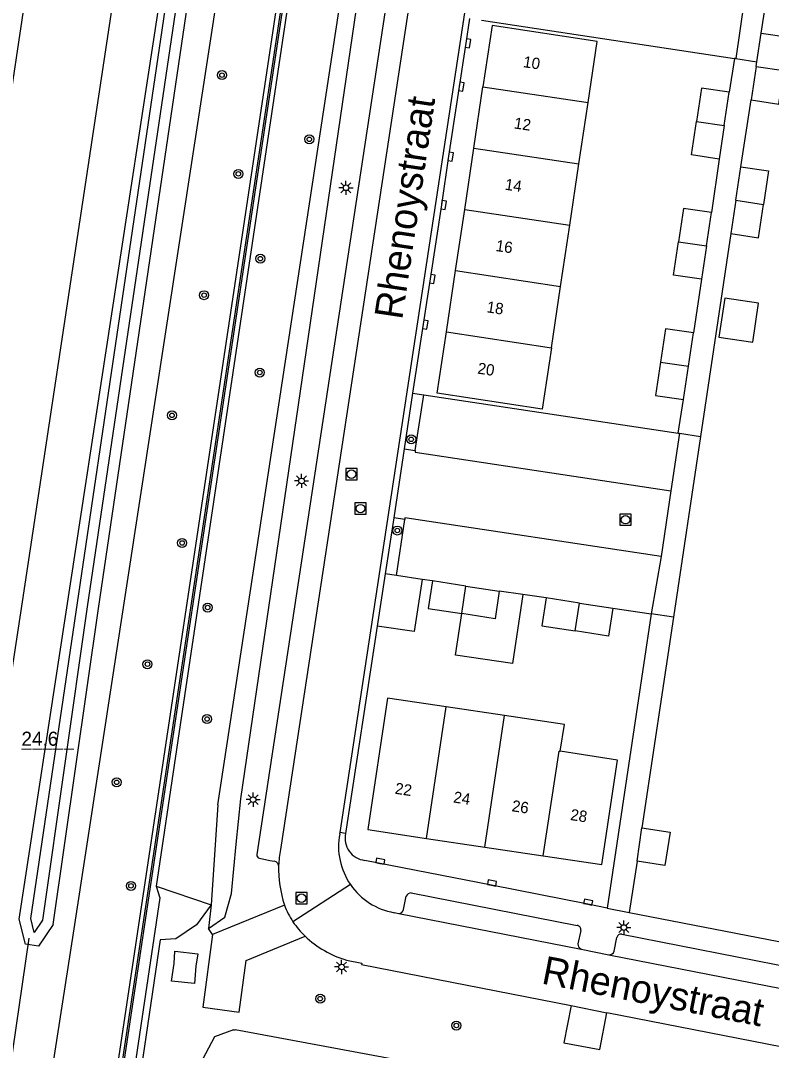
# Model space of a CAD drawing. Extents: x 124000 to 128010, y 398999 to 403000.
# Drawn here: x 126320.1 to 126386.8, y 399650.9 to 399742.3 of the extents above; entities that cross this region are included whole.
import ezdxf

# ---------------------------------------------------------------- set-up
doc = ezdxf.new("R2010")
doc.units = 0
for name, color, linetype in [('gg-afsc-erfafscheiding', 7, 'Continuous'), ('gg-afsc-geluidsscherm', 7, 'Continuous'), ('gg-afsc-hekwerk', 7, 'Continuous'), ('gg-anno-huisnummerreeks BGT', 7, 'Continuous'), ('gg-anno-openbare ruimte label', 7, 'Continuous'), ('gg-bbg-bijgebouw', 7, 'Continuous'), ('gg-bbg-gedigitaliseerde bijgebouw', 7, 'Continuous'), ('gg-bbg-hoofdgebouw', 7, 'Continuous'), ('gg-bbg-lage trafo', 7, 'Continuous'), ('gg-bbg-luifel en loopbrug', 7, 'Continuous'), ('gg-bbg-tussenscheiding', 7, 'Continuous'), ('gg-knt-BGT kruinlijn', 7, 'Continuous'), ('gg-knt-bovenkant onderkant talud', 7, 'Continuous'), ('gg-knt-verharding', 7, 'Continuous'), ('gg-knt-verharding nz', 7, 'Continuous'), ('gg-kntw-bovenkant insteek waterloop', 7, 'Continuous'), ('gg-kntw-waterlijn', 7, 'Continuous'), ('gg-kwrk-duiker nz buis', 7, 'Continuous'), ('gt-anno-nummer hm paal', 7, 'Continuous'), ('gt-grn-groengrens', 7, 'Continuous'), ('gt-grn-weggrens', 7, 'Continuous'), ('gt-symb-boom', 7, 'Continuous'), ('gt-symb-hm paal', 7, 'Continuous'), ('gt-symb-kolk', 7, 'Continuous'), ('gt-symb-lichtmast', 7, 'Continuous'), ('gt-symb-rioolschacht', 7, 'Continuous'), ('gx-grn-maaiveld', 7, 'Continuous')]:
    doc.layers.add(name, color=color, linetype=linetype)

# ---------------------------------------------------------------- blocks, each defined once
blk = doc.blocks.new('gt0-BOOM')
at = {"layer": 'gt-symb-boom'}
for radius in [0.4, 0.2]:
    blk.add_circle((0, 0), radius, dxfattribs=at)
blk = doc.blocks.new('gt0-RS')
at = {"layer": 'gt-symb-rioolschacht'}
blk.add_lwpolyline([(-0.5, -0.5), (0.5, -0.5), (0.5, 0.5), (-0.5, 0.5)], close=True, dxfattribs=at)
blk.add_circle((0, 0), 0.375, dxfattribs=at)
blk = doc.blocks.new('gt0-KOLK')
at = {"layer": 'gt-symb-kolk'}
blk.add_lwpolyline([(0, 0), (0.375, 0), (0.375, 0.4), (-0.375, 0.4), (-0.375, 0), (0, 0)], dxfattribs=at)
blk = doc.blocks.new('gt0-LMAST')
at = {"layer": 'gt-symb-lichtmast'}
for p, q in [((-0.182, 0.173), (-0.447, 0.438)), ((-0.005, 0.246), (-0.005, 0.621)), ((0.172, 0.173), (0.437, 0.438)), ((-0.255, -0.004), (-0.63, -0.004)), ((-0.182, -0.181), (-0.447, -0.446)), ((-0.005, -0.254), (-0.005, -0.629)), ((0.437, -0.446), (0.172, -0.181)), ((0.245, -0.004), (0.62, -0.004))]:
    blk.add_line(p, q, dxfattribs=at)
blk.add_circle((-0.005, -0.004), 0.25, dxfattribs=at)

msp = doc.modelspace()

# ---------------------------------------------------------------- linework, layer by layer
at = {"layer": 'gg-afsc-erfafscheiding'}
msp.add_line((126354.925, 399709.208), (126355.932, 399709.051), dxfattribs=at)
at = {"layer": 'gg-afsc-geluidsscherm'}
for points in [[(126433.522, 399396.193), (126294.266, 399417.89), (126294.312, 399418.568), (126384.69, 400018.495), (126392.393, 400081.874), (126401.389, 400173.179), (126405.812, 400237.067), (126415.183, 400254.387), (126416.933, 400270.191), (126421.505, 400378.061), (126422.448, 400394.046), (126423.962, 400411.149), (126518.093, 400411.476), (126531.613, 400399.449), (126531.513, 400399.337)], [(126433.522, 399396.193), (126433.545, 399396.341), (126294.438, 399418.015), (126294.46, 399418.546), (126384.838, 400018.472), (126392.542, 400081.856), (126401.538, 400173.164), (126405.962, 400237.057), (126415.315, 400254.315), (126417.082, 400270.175), (126421.655, 400378.055), (126422.598, 400394.037), (126424.098, 400410.986), (126518.093, 400411.326), (126531.513, 400399.337)]]:
    msp.add_lwpolyline(points, dxfattribs=at)
at = {"layer": 'gg-afsc-hekwerk'}
for p, q in [((126385.859, 399741.164), (126386.316, 399744.206)), ((126384.062, 399729.288), (126384.963, 399735.23)), ((126382.14, 399729.98), (126381.438, 399725.232)), ((126383.164, 399723.354), (126380.473, 399705.355)), ((126380.55, 399719.305), (126379.841, 399714.554)), ((126380.473, 399705.355), (126378.074, 399689.313)), ((126366.765, 399691.018), (126364.705, 399691.322)), ((126378.074, 399689.313), (126375.279, 399670.617)), ((126374.847, 399667.652), (126374.143, 399663.098)), ((126374.143, 399663.098), (126388.339, 399660.336))]:
    msp.add_line(p, q, dxfattribs=at)
at = {"layer": 'gg-bbg-bijgebouw'}
for p, q in [((126385.475, 399738.618), (126385.859, 399741.164)), ((126385.859, 399741.164), (126388.311, 399740.794)), ((126385.411, 399738.197), (126384.963, 399735.23)), ((126385.411, 399738.197), (126385.475, 399738.618)), ((126382.585, 399732.943), (126383.03, 399735.906)), ((126382.585, 399732.943), (126382.14, 399729.98)), ((126383.613, 399726.321), (126384.062, 399729.288)), ((126383.613, 399726.321), (126383.164, 399723.354)), ((126380.994, 399722.269), (126381.438, 399725.232)), ((126380.994, 399722.269), (126380.55, 399719.305)), ((126379.396, 399711.591), (126379.841, 399714.554)), ((126378.95, 399708.628), (126379.396, 399711.591)), ((126359.652, 399692.079), (126356.689, 399692.526)), ((126359.652, 399692.079), (126362.615, 399691.631)), ((126369.729, 399690.56), (126366.765, 399691.018)), ((126369.729, 399690.56), (126372.692, 399690.103)), ((126374.847, 399667.652), (126375.279, 399670.617)), ((126377.299, 399667.261), (126374.847, 399667.652))]:
    msp.add_line(p, q, dxfattribs=at)
for points in [[(126384.963, 399735.23), (126387.415, 399734.86), (126387.863, 399737.827)], [(126383.03, 399735.906), (126380.568, 399736.276), (126380.123, 399733.313)], [(126382.14, 399729.98), (126379.678, 399730.35), (126380.123, 399733.313)], [(126384.062, 399729.288), (126386.515, 399728.917), (126386.066, 399725.949)], [(126383.164, 399723.354), (126385.617, 399722.981), (126386.066, 399725.949)], [(126381.438, 399725.232), (126378.975, 399725.601), (126378.531, 399722.638)], [(126380.55, 399719.305), (126378.087, 399719.674), (126378.531, 399722.638)], [(126379.841, 399714.554), (126377.376, 399714.921), (126376.935, 399711.958)], [(126376.935, 399711.958), (126376.493, 399708.994), (126378.95, 399708.628)], [(126356.689, 399692.526), (126356.319, 399690.075), (126359.285, 399689.627)], [(126362.615, 399691.631), (126362.25, 399689.179), (126359.285, 399689.627)], [(126366.765, 399691.018), (126366.384, 399688.55), (126369.347, 399688.092)], [(126372.692, 399690.103), (126372.309, 399687.635), (126369.347, 399688.092)], [(126375.279, 399670.617), (126377.771, 399670.22), (126377.299, 399667.261)]]:
    msp.add_lwpolyline(points, dxfattribs=at)
at = {"layer": 'gg-bbg-gedigitaliseerde bijgebouw'}
msp.add_lwpolyline([(126382.114, 399714.166), (126385.119, 399713.721), (126385.631, 399717.179), (126382.626, 399717.624), (126382.114, 399714.166)], dxfattribs=at)
at = {"layer": 'gg-bbg-hoofdgebouw'}
for p, q in [((126360.357, 399730.95), (126361.166, 399736.391)), ((126369.683, 399729.544), (126370.498, 399734.983)), ((126359.547, 399725.51), (126360.357, 399730.95)), ((126368.867, 399724.105), (126369.683, 399729.544)), ((126358.737, 399720.07), (126359.547, 399725.51)), ((126368.051, 399718.666), (126368.867, 399724.105)), ((126357.928, 399714.629), (126358.737, 399720.07)), ((126367.236, 399713.227), (126368.051, 399718.666)), ((126363.087, 399680.578), (126357.9, 399681.356)), ((126356.15, 399669.683), (126361.337, 399668.906)), ((126361.337, 399668.906), (126366.524, 399668.128))]:
    msp.add_line(p, q, dxfattribs=at)
for points in [[(126370.498, 399734.983), (126371.314, 399740.422), (126361.976, 399741.831), (126361.166, 399736.391)], [(126367.236, 399713.227), (126366.42, 399707.788), (126357.118, 399709.189), (126357.928, 399714.629)], [(126357.9, 399681.356), (126352.71, 399682.135), (126350.963, 399670.461), (126356.15, 399669.683)], [(126368.026, 399677.414), (126368.39, 399679.782), (126363.087, 399680.578)], [(126366.524, 399668.128), (126371.711, 399667.35), (126373.104, 399676.624), (126368.026, 399677.414)]]:
    msp.add_lwpolyline(points, dxfattribs=at)
at = {"layer": 'gg-bbg-lage trafo'}
msp.add_lwpolyline([(126333.543, 399657.013), (126333.77, 399658.569), (126333.839, 399659.673), (126335.872, 399659.44), (126335.679, 399658.351), (126335.557, 399656.786), (126333.543, 399657.013)], dxfattribs=at)
at = {"layer": 'gg-bbg-luifel en loopbrug'}
for p, q in [((126352.494, 399693.17), (126351.784, 399688.516)), ((126353.498, 399693.015), (126352.494, 399693.17)), ((126355.759, 399692.669), (126353.498, 399693.015)), ((126364.705, 399691.322), (126362.615, 399691.631))]:
    msp.add_line(p, q, dxfattribs=at)
for points in [[(126355.759, 399692.669), (126355.072, 399688.03), (126351.784, 399688.516)], [(126364.705, 399691.322), (126363.798, 399685.196), (126358.74, 399685.945), (126359.285, 399689.627)]]:
    msp.add_lwpolyline(points, dxfattribs=at)
at = {"layer": 'gg-bbg-tussenscheiding'}
for p, q in [((126385.411, 399738.197), (126387.863, 399737.827)), ((126361.166, 399736.391), (126370.498, 399734.983)), ((126380.123, 399733.313), (126382.585, 399732.943)), ((126360.357, 399730.95), (126369.683, 399729.544)), ((126383.613, 399726.321), (126386.066, 399725.949)), ((126359.547, 399725.51), (126368.867, 399724.105)), ((126378.531, 399722.638), (126380.994, 399722.269)), ((126358.737, 399720.07), (126368.051, 399718.666)), ((126357.928, 399714.629), (126367.236, 399713.227)), ((126376.935, 399711.958), (126379.396, 399711.591)), ((126359.285, 399689.627), (126359.652, 399692.079)), ((126369.347, 399688.092), (126369.729, 399690.56)), ((126356.15, 399669.683), (126357.9, 399681.356)), ((126361.337, 399668.906), (126363.087, 399680.578))]:
    msp.add_line(p, q, dxfattribs=at)
msp.add_lwpolyline([(126366.524, 399668.128), (126367.919, 399677.43), (126368.026, 399677.414)], dxfattribs=at)
at = {"layer": 'gg-knt-BGT kruinlijn'}
for points in [[(126300.242, 399460.061), (126317.155, 399573.618), (126327.853, 399643.472), (126345.991, 399764.256), (126377.209, 399971.201), (126384.168, 400018.601), (126391.597, 400079.17), (126401.015, 400171.969), (126405.272, 400237.075), (126405.836, 400239.447)], [(126405.997, 400230.826), (126401.252, 400165.313), (126397.513, 400125.164), (126394.977, 400098.805), (126384.91, 400016.956), (126372.958, 399936.144), (126361.724, 399862.808), (126350.889, 399790.817), (126334.29, 399679.75), (126332.168, 399665.424)], [(126332.168, 399665.424), (126332.505, 399664.403), (126326.997, 399627.412), (126326.354, 399625.57), (126325.748, 399624.249), (126321.63, 399595.513), (126311.054, 399526.142)]]:
    msp.add_lwpolyline(points, dxfattribs=at)
at = {"layer": 'gg-knt-bovenkant onderkant talud'}
for points in [[(126293.229, 399462.196), (126310.804, 399577.419), (126321.785, 399641.664), (126324.83, 399661.281), (126341.384, 399769.192), (126355.148, 399863.606), (126371.991, 399972.892), (126378.989, 400019.753), (126385.648, 400077.466), (126395.494, 400171.208), (126398.482, 400218.678), (126399.195, 400237.176), (126399.855, 400244.875), (126401.075, 400247.387), (126403.954, 400253.411), (126406.57, 400258.304), (126407.848, 400260.608), (126408.109, 400271.651), (126414.004, 400375.395), (126416.291, 400410.556)], [(126337.055, 399663.773), (126335.755, 399661.999), (126333.916, 399660.765), (126332.52, 399660.668), (126328.5, 399633.374), (126331.078, 399632.608), (126332.337, 399630.998), (126332.355, 399628.505), (126332.067, 399624.359)]]:
    msp.add_lwpolyline(points, dxfattribs=at)
at = {"layer": 'gg-knt-verharding'}
for p, q in [((126358.524, 399782.884), (126341.103, 399668.24)), ((126365.333, 399781.244), (126348.47, 399670.193)), ((126361.027, 399742.312), (126383.477, 399738.908)), ((126383.477, 399738.908), (126383.03, 399735.906)), ((126354.925, 399709.208), (126354.184, 399704.255)), ((126355.164, 399704.1), (126355.932, 399709.051)), ((126355.932, 399709.051), (126378.483, 399705.646)), ((126378.483, 399705.646), (126378.95, 399708.628)), ((126354.184, 399704.255), (126353.264, 399698.132)), ((126354.184, 399704.255), (126355.164, 399704.1)), ((126353.264, 399698.132), (126352.494, 399693.17)), ((126354.227, 399697.992), (126353.264, 399698.132)), ((126353.498, 399693.015), (126354.227, 399697.992)), ((126356.689, 399692.526), (126355.759, 399692.669)), ((126376.102, 399689.608), (126372.187, 399663.477)), ((126372.692, 399690.103), (126376.102, 399689.608)), ((126351.784, 399688.516), (126348.979, 399670.116)), ((126348.47, 399670.193), (126348.452, 399670.077)), ((126354.808, 399664.855), (126369.532, 399661.949)), ((126354.107, 399663.362), (126354.346, 399664.56)), ((126343.55, 399663.755), (126337.181, 399661.137)), ((126353.283, 399663.086), (126353.692, 399663.023)), ((126369.841, 399661.511), (126369.601, 399660.328)), ((126373.493, 399661.176), (126392.88, 399657.377)), ((126372.803, 399659.672), (126373.045, 399660.867)), ((126369.889, 399659.857), (126372.35, 399659.355)), ((126368.983, 399654.835), (126372.169, 399654.21))]:
    msp.add_line(p, q, dxfattribs=at)
for points in [[(126367.407, 400062.712), (126364.322, 400037.875), (126361.171, 400013.803), (126357.829, 399990.064), (126353.282, 399959.93), (126347.871, 399924.53), (126341.915, 399884.96), (126328.842, 399798.709), (126320.556, 399744.349), (126316.646, 399718.33), (126308.838, 399667.237), (126306.683, 399653.03)], [(126375.086, 400061.828), (126371.995, 400036.99), (126368.895, 400013.208), (126365.235, 399987.425), (126360.949, 399959.247), (126355.621, 399923.874), (126349.501, 399883.525), (126345.75, 399858.978), (126340.485, 399824.032), (126332.179, 399769.496), (126320.274, 399690.665), (126316.376, 399665.179), (126314.314, 399651.556)], [(126359.971, 399742.46), (126359.648, 399740.27), (126358.108, 399730.22), (126357.475, 399725.922), (126356.48, 399719.357), (126354.925, 399709.208)], [(126341.332, 399667.91), (126342.253, 399667.727), (126342.674, 399667.655)], [(126372.187, 399663.477), (126370.46, 399663.829), (126361.934, 399665.524), (126350.683, 399667.726)], [(126337.181, 399661.137), (126336.308, 399654.686), (126339.521, 399654.242), (126340.158, 399658.849), (126345.381, 399661.006)], [(126349.07, 399658.868), (126350.412, 399658.601), (126350.392, 399658.482), (126368.983, 399654.835)], [(126368.983, 399654.835), (126368.337, 399651.539), (126371.526, 399650.931), (126372.169, 399654.21)]]:
    msp.add_lwpolyline(points, dxfattribs=at)
for centre, radius, start, end in [((126354.336, 399668.979), 5.985, 169.42979, 214.65017), ((126350.914, 399669.693), 1.98, 167.66224, 263.31327), ((126341.409, 399668.208), 0.308, 174.02699, 255.48962), ((126342.592, 399667.217), 0.446, 7.50771, 79.39598), ((126353.729, 399667.045), 10.698, 178.76805, 197.91124), ((126354.336, 399668.977), 5.985, 214.63463, 259.8635), ((126354.898, 399664.205), 0.656, 97.85434, 147.26441), ((126350.513, 399666.401), 7.449, 200.80731, 213.6179), ((126353.704, 399663.432), 0.409, 268.2899, 350.19863), ((126350.499, 399666.405), 7.44, 213.7054, 226.5325), ((126369.494, 399661.594), 0.357, 346.57793, 83.82644), ((126373.412, 399660.815), 0.37, 77.30992, 171.88064), ((126351.573, 399667.439), 8.929, 226.09177, 253.71843), ((126370.015, 399660.258), 0.42, 170.33419, 252.55446), ((126372.39, 399659.78), 0.427, 264.61356, 345.3535)]:
    msp.add_arc(centre, radius, start, end, dxfattribs=at)
at = {"layer": 'gg-knt-verharding nz'}
for p, q in [((126360.622, 399783.283), (126343.194, 399668.685)), ((126384.357, 399744.016), (126383.599, 399738.898)), ((126383.599, 399738.898), (126383.477, 399738.908)), ((126378.597, 399705.635), (126377.843, 399700.526)), ((126378.483, 399705.646), (126378.597, 399705.635)), ((126377.843, 399700.526), (126376.971, 399694.698)), ((126376.971, 399694.698), (126376.102, 399689.608)), ((126348.979, 399670.116), (126348.47, 399670.193)), ((126353.692, 399663.023), (126369.889, 399659.857)), ((126372.35, 399659.355), (126393.193, 399655.272))]:
    msp.add_line(p, q, dxfattribs=at)
for points in [[(126355.164, 399704.1), (126355.148, 399703.962), (126377.843, 399700.526)], [(126376.971, 399694.698), (126354.241, 399698.118), (126354.227, 399697.992)]]:
    msp.add_lwpolyline(points, dxfattribs=at)
msp.add_arc((126355.025, 399666.628), 12.009, 170.13884, 176.91325, dxfattribs=at)
at = {"layer": 'gg-kntw-bovenkant insteek waterloop'}
for p, q in [((126337.653, 399672.667), (126337.055, 399663.773)), ((126337.055, 399663.773), (126336.819, 399661.669))]:
    msp.add_line(p, q, dxfattribs=at)
for points in [[(126323.031, 399662.04), (126321.74, 399660.117), (126320.587, 399660.289), (126320.014, 399662.511), (126332.334, 399743.098), (126336.188, 399768.41), (126344.467, 399823.06), (126353.306, 399883.083), (126359.695, 399923.364), (126365.113, 399959.07), (126369.177, 399986.373), (126372.735, 400012.848), (126375.768, 400035.991), (126379.045, 400062.476), (126382.001, 400085.384), (126384.826, 400114.553), (126387.163, 400137.912), (126389.716, 400166.128), (126391.77, 400193.942), (126393.76, 400220.612), (126395.587, 400247.464), (126396.695, 400267.432)], [(126323.031, 399662.04), (126327.041, 399690.098), (126334.838, 399742.841), (126338.537, 399768.285), (126342.893, 399797.119), (126346.686, 399823.411), (126352.294, 399859.144), (126356.486, 399884.03), (126360.061, 399908.445), (126363.653, 399932.302), (126367.208, 399956.505), (126370.042, 399973.218), (126373.244, 399995.515), (126376.51, 400018.7), (126379.574, 400041.751), (126382.631, 400066.119), (126383.672, 400073.796)], [(126337.653, 399672.667), (126358.597, 399810.023), (126360.759, 399823.044), (126366.579, 399863.454), (126372.003, 399897.554), (126376.599, 399928.428), (126377.154, 399929.924)], [(126339.685, 399673.178), (126359.685, 399809.893), (126360.254, 399811.76)], [(126336.819, 399661.669), (126338.257, 399662.686), (126338.863, 399664.787), (126339.261, 399669.177), (126339.685, 399673.178)], [(126339.034, 399652.698), (126337.335, 399652.079), (126336.286, 399650.066), (126335.46, 399648.124), (126334.803, 399644.783), (126334.618, 399641.802), (126334.699, 399639.737), (126335.116, 399638.135)], [(126391.937, 399642.759), (126361.932, 399648.444), (126339.174, 399652.673)]]:
    msp.add_lwpolyline(points, dxfattribs=at)
at = {"layer": 'gg-kntw-waterlijn'}
for points in [[(126322.073, 399662.408), (126321.351, 399661.331), (126321.033, 399662.562), (126332.954, 399743.212), (126336.808, 399768.525), (126345.446, 399825.528), (126354.295, 399882.932), (126360.683, 399923.211), (126366.102, 399958.921), (126370.167, 399986.233), (126373.726, 400012.716), (126376.76, 400035.865), (126380.037, 400062.351), (126382.262, 400073.983), (126384.138, 400089.122), (126386.6, 400114.4), (126388.846, 400137.708), (126391.398, 400165.952), (126393.748, 400192.659), (126395.378, 400220.459), (126397.199, 400247.7), (126398.164, 400265.142), (126398.387, 400267.099)], [(126396.316, 400215.111), (126394.753, 400190.156), (126392.641, 400165.901), (126390.957, 400143.335), (126388.243, 400118.036), (126385.3, 400093.236), (126381.639, 400066.248), (126378.582, 400041.879), (126375.519, 400018.836), (126372.254, 399995.656), (126369.054, 399973.373), (126366.22, 399956.661), (126362.664, 399932.449), (126359.072, 399908.592), (126355.498, 399884.186), (126351.307, 399859.305), (126345.697, 399823.56), (126341.904, 399797.265), (126337.548, 399768.432), (126333.849, 399742.986), (126326.051, 399690.242), (126322.073, 399662.408)]]:
    msp.add_lwpolyline(points, dxfattribs=at)
at = {"layer": 'gg-kwrk-duiker nz buis'}
msp.add_line((126317.255, 399635.883), (126320.911, 399660.819), dxfattribs=at)
at = {"layer": 'gt-grn-groengrens'}
for p, q in [((126332.168, 399665.424), (126337.055, 399663.773)), ((126337.181, 399661.137), (126336.819, 399661.669))]:
    msp.add_line(p, q, dxfattribs=at)
at = {"layer": 'gt-grn-weggrens'}
for p, q in [((126383.599, 399738.898), (126385.475, 399738.618)), ((126378.597, 399705.635), (126380.473, 399705.355)), ((126378.074, 399689.313), (126376.102, 399689.608)), ((126349.412, 399665.576), (126344.31, 399662.277)), ((126372.187, 399663.477), (126374.143, 399663.098))]:
    msp.add_line(p, q, dxfattribs=at)
at = {"layer": 'gx-grn-maaiveld'}
msp.add_line((126339.034, 399652.698), (126339.174, 399652.673), dxfattribs=at)
msp.add_lwpolyline([(126406.168, 399647.544), (126403.179, 399648.141), (126372.169, 399654.21)], dxfattribs=at)

# ---------------------------------------------------------------- block references
at = {"layer": 'gt-symb-boom'}
for p in [(126338.012, 399737.427), (126345.755, 399731.732), (126339.464, 399728.659), (126341.418, 399721.135), (126336.421, 399717.894), (126341.364, 399711.026), (126333.568, 399707.233), (126354.801, 399705.099), (126353.565, 399697.006), (126334.473, 399695.904), (126336.737, 399690.168), (126331.397, 399685.14), (126336.687, 399680.273), (126328.662, 399674.656), (126329.929, 399665.464), (126346.725, 399655.45), (126358.812, 399653.066)]:
    msp.add_blockref('gt0-BOOM', p, dxfattribs=at)
at = {"layer": 'gt-symb-kolk'}
for p, rotation in [((126359.648, 399740.27), -98.7657956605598), ((126359.055, 399736.424), -98.70075857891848), ((126358.108, 399730.22), -98.36635579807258), ((126357.475, 399725.922), -98.6185494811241), ((126356.48, 399719.357), -98.69278111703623), ((126355.862, 399715.317), -98.72468892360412), ((126352.021, 399667.46), -11.051952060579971), ((126361.934, 399665.524), -11.240298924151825), ((126370.46, 399663.829), -11.52832765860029)]:
    msp.add_blockref('gt0-KOLK', p, dxfattribs=dict(at, rotation=rotation))
at = {"layer": 'gt-symb-lichtmast'}
for p in [(126349.016, 399727.428), (126345.078, 399701.409), (126340.775, 399673.12), (126373.678, 399661.768), (126348.627, 399658.268)]:
    msp.add_blockref('gt0-LMAST', p, dxfattribs=at)
at = {"layer": 'gt-symb-rioolschacht'}
for p in [(126349.501, 399702.01), (126350.299, 399698.95), (126373.812, 399697.966), (126345.069, 399664.371)]:
    msp.add_blockref('gt0-RS', p, dxfattribs=at)

# ---------------------------------------------------------------- texts
at = {"layer": 'gg-anno-huisnummerreeks BGT'}
for s, p in [('10', (126364.685, 399738.142)), ('12', (126363.876, 399732.702)), ('14', (126363.066, 399727.261)), ('16', (126362.256, 399721.821)), ('18', (126361.447, 399716.381)), ('20', (126360.637, 399710.94)), ('22', (126353.308, 399673.649)), ('24', (126358.494, 399672.871)), ('26', (126363.682, 399672.094)), ('28', (126368.869, 399671.316))]:
    msp.add_text(s, height=1, rotation=351.5, dxfattribs=at).set_placement(p)
at = {"layer": 'gg-anno-openbare ruimte label'}
for rotation, p in [(81.5, (126353.996, 399715.656)), (348.9, (126366.277, 399656.814))]:
    msp.add_text('Rhenoystraat', height=2.5, rotation=rotation, dxfattribs=at).set_placement(p)
at = {"layer": 'gt-anno-nummer hm paal'}
msp.add_text('24.6', height=1.25, dxfattribs=at).set_placement((126320.221, 399677.901))
at = {"layer": 'gt-symb-hm paal'}
msp.add_text('_____', height=1.25, dxfattribs=at).set_placement((126320.221, 399677.901))

doc.saveas('drawing.dxf')
